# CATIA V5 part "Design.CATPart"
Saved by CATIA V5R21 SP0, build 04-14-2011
Part number: Part1
Material "DS Red": density 7860 kg/m3, Young's modulus 2e+11 Pa, Poisson ratio 0.266
Bounding box of the stored display mesh (mm): x 0 to 25, y -95.5 to 95.5, z -95.5 to 95.5
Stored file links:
  G:\CATIA\Class\Design.CATPart
  C:\Program Files (x86)\Dassault Systemes\B21\intel_a\startup\materials\red_env_512x512.jpg
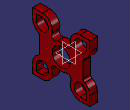
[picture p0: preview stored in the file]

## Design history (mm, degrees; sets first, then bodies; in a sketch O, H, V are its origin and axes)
Body1 (main body), material "DS Red"
  Sketch1 on yz-plane, origin (0, 0, 0), H (0, 1, 0), V (0, 0, 1)
    circle A1 centre (0, 0) radius 30
    arc A2 centre (63, -63) radius 32.5 from (95.5, -63) to (73, -32.0767) ccw
    point P1 (63, -63)
    line L1 (95.5, -63) -> (95.5, -95.5)
    line L2 (95.5, -95.5) -> (63, -95.5)
    point P2 (95.5, -30.5)
    point P3 (95.5, -95.5)
    arc A3 centre (63, -63) radius 20.2 from (83.2, -63) to (63, -83.2) ccw
    construction line L3 (95.5, -63) -> (83.2, -63)
    construction line L4 (63, -95.5) -> (63, -83.2)
    line L5 (83.2, -83.2) -> (83.2, -63)
    point P9 (83.2, -63)
    line L6 (83.2, -83.2) -> (63, -83.2)
    point P10 (63, -83.2)
    point P12 (30.5, 95.5)
    arc A4 centre (63, 63) radius 32.5 from (63, 95.5) to (32.2173, 52.5751) ccw
    line L7 (63, 95.5) -> (95.5, 95.5)
    line L8 (95.5, 95.5) -> (95.5, 63)
    arc A5 centre (63, 63) radius 20.2 from (63, 83.2) to (83.2, 63) ccw
    line L9 (83.2, 83.2) -> (63, 83.2)
    line L10 (83.2, 83.2) -> (83.2, 63)
    point P22 (-95.5, 30.5)
    arc A6 centre (-63, 63) radius 32.5 from (-95.5, 63) to (-73, 32.0767) ccw
    line L11 (-95.5, 63) -> (-95.5, 95.5)
    line L12 (-95.5, 95.5) -> (-63, 95.5)
    arc A7 centre (-63, 63) radius 20.2 from (-83.2, 63) to (-63, 83.2) ccw
    line L13 (-83.2, 83.2) -> (-83.2, 63)
    line L14 (-83.2, 83.2) -> (-63, 83.2)
    point P32 (-30.5, -95.5)
    arc A8 centre (-63, -63) radius 32.5 from (-63, -95.5) to (-32.2173, -52.5751) ccw
    line L15 (-63, -95.5) -> (-95.5, -95.5)
    line L16 (-95.5, -95.5) -> (-95.5, -63)
    arc A9 centre (-63, -63) radius 20.2 from (-63, -83.2) to (-83.2, -63) ccw
    line L17 (-83.2, -83.2) -> (-63, -83.2)
    line L18 (-83.2, -83.2) -> (-83.2, -63)
    point P41 (95.5, -30.5)
    line L19 (-73, -32.0767) -> (-73, 32.0767)
    point P43 (-73, -32.0767)
    line L20 (73, 32.0767) -> (73, -32.0767)
    point P45 (73, 32.0767)
    arc A10 centre (20.8514, -48.7259) radius 12 from (32.2173, -52.5751) to (16.1304, -37.6937) ccw
    point P48 (32.2173, -52.5751)
    arc A11 centre (20.8514, 48.7259) radius 12 from (32.2173, 52.5751) to (16.1304, 37.6937) cw
    arc A12 centre (-20.8514, 48.7259) radius 12 from (-32.2173, 52.5751) to (-16.1304, 37.6937) ccw
    arc A13 centre (-20.8514, -48.7259) radius 12 from (-32.2173, -52.5751) to (-16.1304, -37.6937) cw
    arc A14 centre (-63, 63) radius 32.5 from (-32.2173, 52.5751) to (-63, 95.5) ccw
    arc A15 centre (0, 0) radius 41 from (-16.1304, -37.6937) to (16.1304, -37.6937) ccw
    arc A16 centre (-63, -63) radius 32.5 from (-73, -32.0767) to (-95.5, -63) ccw
    arc A17 centre (0, 0) radius 41 from (16.1304, 37.6937) to (-16.1304, 37.6937) ccw
    arc A18 centre (63, -63) radius 32.5 from (32.2173, -52.5751) to (63, -95.5) ccw
    arc A19 centre (63, 63) radius 32.5 from (73, 32.0767) to (95.5, 63) ccw
    radius A1 = 30
    radius A2 = 32.5
    distance P2 P3 = 65
    distance A2 A3 = 12.3
    distance P1 H = 63
    distance P9 H = 63
    distance P1 V = 63
    distance P10 V = 63
    radius A10 = 12
    horizontal: L2 H
    vertical: L1 V, L19 V, L20 V
    tangency: L2 A2, A2 L1, A10 A2
    concentricity: A2 A3
    coincidence: L3 P1, L4 P1, A8 P43, A4 P45, A2 P48, A6 A14, A8 A16, A2 A18, A4 A19
  Pad1: profile Sketch1, direction (1, 0, 0), length 25
  Fillet1: radius 10, on edge [face of Pad1 from Sketch1.L19 | face of Pad1 from Sketch1.A6]; edge [face of Pad1 from Sketch1.A16 | face of Pad1 from Sketch1.L19]; edge [face of Pad1 from Sketch1.A19 | face of Pad1 from Sketch1.L20]; edge [face of Pad1 from Sketch1.L20 | face of Pad1 from Sketch1.A2]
